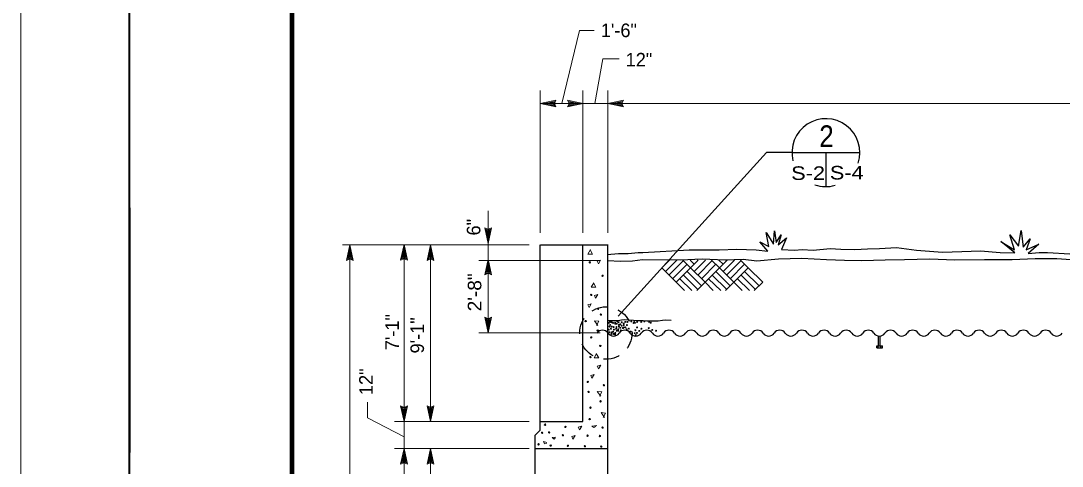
# Model space of a CAD drawing. Extents: x -22.3 to 19.7, y -11.8 to 18.2.
# Drawn here: x -22.31 to -12.72, y -5.16 to -1.06 of the extents above; entities that cross this region are included whole.
import ezdxf
from ezdxf.enums import TextEntityAlignment as Align

# ---------------------------------------------------------------- set-up
doc = ezdxf.new("R2010")
doc.units = 0
doc.header["$LTSCALE"] = 0.05
doc.linetypes.add('MEDIUM_DASHED', pattern=[4.5, 3, -1.5])
doc.layers.add('1', color=7, linetype='Continuous', lineweight=13)
doc.layers.add('2', color=7, linetype='Continuous', lineweight=13)

msp = doc.modelspace()

# ---------------------------------------------------------------- linework, layer by layer
at = {"layer": '1'}
for p, q in [((-22.30942, -11.83969), (-22.30942, 18.16031)), ((-17.32642, -1.82369), (-17.16442, -1.15069)), ((-17.16442, -1.15069), (-17.02842, -1.15069)), ((-17.02242, -1.82369), (-16.94842, -1.41369)), ((-16.94842, -1.41369), (-16.79842, -1.41369)), ((-17.52542, -3.01369), (-17.52542, -1.70369)), ((-17.13242, -3.01369), (-17.13242, -1.70369)), ((-16.90342, -3.01369), (-16.90342, -1.70369)), ((-17.52542, -1.82369), (-17.38142, -1.79269)), ((-17.48842, -1.82369), (-17.39442, -1.80369)), ((-17.45242, -1.82369), (-17.40742, -1.81369)), ((-17.40742, -1.81369), (-17.41142, -1.82369)), ((-17.39442, -1.80369), (-17.40342, -1.82369)), ((-17.13042, -1.82369), (-17.27442, -1.79269)), ((-17.16742, -1.82369), (-17.26142, -1.80369)), ((-17.25242, -1.82369), (-17.26142, -1.80369)), ((-17.20342, -1.82369), (-17.24842, -1.81469)), ((-17.24442, -1.82369), (-17.24842, -1.81469)), ((-16.90342, -1.82369), (-16.75942, -1.79269)), ((-16.86642, -1.82369), (-16.77242, -1.80369)), ((-16.83042, -1.82369), (-16.78542, -1.81369)), ((-16.78542, -1.81369), (-16.78942, -1.82369)), ((-16.77242, -1.80369), (-16.78142, -1.82369)), ((-17.52542, -1.82369), (-17.38142, -1.85469)), ((-17.48842, -1.82369), (-17.39442, -1.84369)), ((-17.45242, -1.82369), (-17.40742, -1.83269)), ((-17.41142, -1.82369), (-17.40742, -1.83269)), ((-17.40342, -1.82369), (-17.39442, -1.84369)), ((-17.13042, -1.82369), (-17.27442, -1.85469)), ((-17.16742, -1.82369), (-17.26142, -1.84369)), ((-17.26142, -1.84369), (-17.25242, -1.82369)), ((-17.20342, -1.82369), (-17.24842, -1.83369)), ((-17.24842, -1.83369), (-17.24442, -1.82369)), ((-16.90342, -1.82369), (-8.80242, -1.82369)), ((-16.90342, -1.82369), (-16.75942, -1.85469)), ((-16.86642, -1.82369), (-16.77242, -1.84369)), ((-16.83042, -1.82369), (-16.78542, -1.83269)), ((-16.78942, -1.82369), (-16.78542, -1.83269)), ((-16.78142, -1.82369), (-16.77242, -1.84369)), ((-18.00642, -3.11069), (-18.03742, -2.96669)), ((-18.00642, -3.11069), (-17.97542, -2.96669)), ((-18.00642, -3.07369), (-18.02642, -2.97969)), ((-18.02642, -2.97969), (-18.00642, -2.98869)), ((-18.00642, -3.03769), (-18.01642, -2.99269)), ((-18.01642, -2.99269), (-18.00642, -2.99669)), ((-18.00642, -3.07369), (-17.98642, -2.97969)), ((-18.00642, -2.98869), (-17.98642, -2.97969)), ((-18.00642, -3.03769), (-17.99742, -2.99269)), ((-18.00642, -2.99669), (-17.99742, -2.99269)), ((-17.62842, -3.12369), (-19.34842, -3.12369)), ((-19.27942, -3.12369), (-19.31042, -3.26769)), ((-19.27942, -3.16069), (-19.29942, -3.25469)), ((-19.27942, -3.12369), (-19.24842, -3.26769)), ((-19.27942, -3.16069), (-19.25942, -3.25469)), ((-18.78042, -3.12169), (-18.81142, -3.26569)), ((-18.78042, -3.15869), (-18.80042, -3.25269)), ((-18.78042, -3.12169), (-18.74942, -3.26569)), ((-18.78042, -3.15869), (-18.76042, -3.25269)), ((-18.53742, -3.12369), (-18.56842, -3.26769)), ((-18.53742, -3.16069), (-18.55742, -3.25469)), ((-18.53742, -4.74869), (-18.53742, -3.12369)), ((-18.53742, -3.12369), (-18.50642, -3.26769)), ((-18.53742, -3.16069), (-18.51742, -3.25469)), ((-19.27942, -3.24569), (-19.29942, -3.25469)), ((-19.27942, -3.19669), (-19.28842, -3.24169)), ((-19.27942, -3.23769), (-19.28842, -3.24169)), ((-19.27942, -3.19669), (-19.26942, -3.24169)), ((-19.26942, -3.24169), (-19.27942, -3.23769)), ((-19.25942, -3.25469), (-19.27942, -3.24569)), ((-18.78042, -3.24369), (-18.80042, -3.25269)), ((-18.78042, -3.19469), (-18.78942, -3.23969)), ((-18.78042, -3.23569), (-18.78942, -3.23969)), ((-18.78042, -3.19469), (-18.77042, -3.23969)), ((-18.77042, -3.23969), (-18.78042, -3.23569)), ((-18.76042, -3.25269), (-18.78042, -3.24369)), ((-18.53742, -3.24569), (-18.55742, -3.25469)), ((-18.53742, -3.19669), (-18.54642, -3.24169)), ((-18.53742, -3.23769), (-18.54642, -3.24169)), ((-18.53742, -3.19669), (-18.52742, -3.24169)), ((-18.52742, -3.24169), (-18.53742, -3.23769)), ((-18.51742, -3.25469), (-18.53742, -3.24569)), ((-18.00642, -3.25569), (-18.03742, -3.39969)), ((-18.00642, -3.25569), (-17.97542, -3.39969)), ((-16.97442, -3.26669), (-18.09242, -3.26669)), ((-18.00642, -3.29269), (-18.02642, -3.38669)), ((-18.00642, -3.32869), (-18.01542, -3.37369)), ((-18.00642, -3.29269), (-17.98642, -3.38669)), ((-18.00642, -3.32869), (-17.99642, -3.37369)), ((-16.40642, -3.33569), (-16.33542, -3.26469)), ((-16.37342, -3.36969), (-16.26942, -3.26469)), ((-16.34042, -3.40269), (-16.20742, -3.26869)), ((-16.30742, -3.43569), (-16.17442, -3.30269)), ((-16.27342, -3.46869), (-16.14142, -3.33569)), ((-16.14142, -3.33569), (-16.21242, -3.26469)), ((-16.10842, -3.30269), (-16.14642, -3.26469)), ((-16.14142, -3.33569), (-16.07042, -3.26469)), ((-16.14142, -3.33569), (-16.07042, -3.26469)), ((-16.00842, -3.46869), (-16.14142, -3.33569)), ((-16.10842, -3.36969), (-16.00342, -3.26469)), ((-16.07542, -3.26869), (-16.07942, -3.26469)), ((-16.07542, -3.40269), (-15.94242, -3.26869)), ((-16.04142, -3.43569), (-15.90942, -3.30269)), ((-16.00842, -3.46869), (-15.87542, -3.33569)), ((-15.87542, -3.33569), (-15.94742, -3.26469)), ((-15.84242, -3.30269), (-15.88042, -3.26469)), ((-15.87542, -3.33569), (-15.80442, -3.26469)), ((-15.84242, -3.36969), (-15.73742, -3.26469)), ((-15.80942, -3.26869), (-15.81342, -3.26469)), ((-15.80942, -3.40269), (-15.67642, -3.26869)), ((-15.77542, -3.43569), (-15.64342, -3.30269)), ((-15.74242, -3.46869), (-15.61042, -3.33569)), ((-15.61042, -3.33569), (-15.68142, -3.26469)), ((-15.47742, -3.46869), (-15.61042, -3.33569)), ((-18.00642, -3.37769), (-18.02642, -3.38669)), ((-18.00642, -3.36969), (-18.01542, -3.37369)), ((-17.99642, -3.37369), (-18.00642, -3.36969)), ((-17.98642, -3.38669), (-18.00642, -3.37769)), ((-16.13142, -3.54569), (-16.24042, -3.43569)), ((-16.07542, -3.53469), (-16.20742, -3.40269)), ((-16.04142, -3.50169), (-16.17442, -3.36969)), ((-15.86442, -3.54569), (-15.97542, -3.43569)), ((-15.80842, -3.53469), (-15.94242, -3.40269)), ((-15.77542, -3.50169), (-15.90942, -3.36969)), ((-15.59942, -3.54569), (-15.70942, -3.43569)), ((-15.54342, -3.53469), (-15.67642, -3.40269)), ((-15.51042, -3.50169), (-15.64342, -3.36969)), ((-16.08542, -3.54569), (-16.00842, -3.46869)), ((-15.93242, -3.54569), (-16.00842, -3.46869)), ((-15.81942, -3.54569), (-15.74242, -3.46869)), ((-15.55442, -3.54569), (-15.47742, -3.46869)), ((-18.00642, -3.93369), (-18.03742, -3.78969)), ((-18.00642, -3.89669), (-18.02642, -3.80269)), ((-18.02642, -3.80269), (-18.00642, -3.81169)), ((-18.00642, -3.86069), (-18.01642, -3.81569)), ((-18.01642, -3.81569), (-18.00642, -3.81969)), ((-18.00642, -3.93369), (-17.97542, -3.78969)), ((-18.00642, -3.89669), (-17.98642, -3.80269)), ((-18.00642, -3.81169), (-17.98642, -3.80269)), ((-18.00642, -3.86069), (-17.99742, -3.81569)), ((-18.00642, -3.81969), (-17.99742, -3.81569)), ((-16.97442, -3.93369), (-18.09242, -3.93369)), ((-18.78042, -4.74969), (-18.81142, -4.60569)), ((-18.78042, -4.71269), (-18.80042, -4.61869)), ((-18.80042, -4.61869), (-18.78042, -4.62769)), ((-18.78042, -4.67669), (-18.79042, -4.63169)), ((-18.79042, -4.63169), (-18.78042, -4.63569)), ((-18.78042, -4.74969), (-18.74942, -4.60569)), ((-18.78042, -4.71269), (-18.76042, -4.61869)), ((-18.78042, -4.62769), (-18.76042, -4.61869)), ((-18.78042, -4.67669), (-18.77142, -4.63169)), ((-18.78042, -4.63569), (-18.77142, -4.63169)), ((-18.53742, -4.74869), (-18.56842, -4.60469)), ((-18.53742, -4.71169), (-18.55742, -4.61769)), ((-18.55742, -4.61769), (-18.53742, -4.62669)), ((-18.53742, -4.67569), (-18.54742, -4.63069)), ((-18.54742, -4.63069), (-18.53742, -4.63469)), ((-18.53742, -4.74869), (-18.50642, -4.60469)), ((-18.53742, -4.71169), (-18.51742, -4.61769)), ((-18.53742, -4.62669), (-18.51742, -4.61769)), ((-18.53742, -4.67569), (-18.52842, -4.63069)), ((-18.53742, -4.63469), (-18.52842, -4.63069)), ((-17.62842, -4.74969), (-18.86842, -4.74969)), ((-17.62842, -4.99969), (-18.86842, -4.99969)), ((-18.78042, -4.99969), (-18.81142, -5.14369)), ((-18.78042, -5.03669), (-18.80042, -5.13069)), ((-18.78042, -5.07269), (-18.78942, -5.11769)), ((-18.78042, -4.99969), (-18.74942, -5.14369)), ((-18.78042, -5.03669), (-18.76042, -5.13069)), ((-18.78042, -5.07269), (-18.77042, -5.11769)), ((-18.53742, -4.99969), (-18.56842, -5.14369)), ((-18.53742, -5.03669), (-18.55742, -5.13069)), ((-18.53742, -5.07269), (-18.54642, -5.11769)), ((-18.53742, -7.65769), (-18.53742, -4.99969)), ((-18.53742, -4.99969), (-18.50642, -5.14369)), ((-18.53742, -5.03669), (-18.51742, -5.13069)), ((-18.53742, -5.07269), (-18.52742, -5.11769)), ((-18.78042, -5.12169), (-18.80042, -5.13069)), ((-18.78042, -5.11369), (-18.78942, -5.11769)), ((-18.77042, -5.11769), (-18.78042, -5.11369)), ((-18.76042, -5.13069), (-18.78042, -5.12169)), ((-18.53742, -5.12169), (-18.55742, -5.13069)), ((-18.53742, -5.11369), (-18.54642, -5.11769)), ((-18.52742, -5.11769), (-18.53742, -5.11369)), ((-18.51742, -5.13069), (-18.53742, -5.12169))]:
    msp.add_line(p, q, dxfattribs=at)
at = {"layer": '1', "lineweight": 25}
for p, q in [((-15.44342, -2.27569), (-16.80842, -3.77969)), ((-15.20742, -2.27569), (-15.44342, -2.27569)), ((-17.52542, -4.82969), (-17.52542, -3.12369)), ((-17.52242, -3.12369), (-16.90142, -3.12369)), ((-17.13242, -4.75069), (-17.13242, -3.12369)), ((-16.90342, -7.91969), (-16.90342, -3.12569)), ((-14.41042, -4.05469), (-14.41042, -3.96369)), ((-14.39442, -4.05469), (-14.39442, -3.96369)), ((-14.42642, -4.05469), (-14.37542, -4.05469)), ((-14.42642, -4.07169), (-14.42642, -4.05469)), ((-14.42642, -4.07169), (-14.37542, -4.07169)), ((-14.41342, -4.07169), (-14.41342, -4.05469)), ((-14.39042, -4.07169), (-14.39042, -4.05469)), ((-14.37542, -4.07169), (-14.37542, -4.05469)), ((-17.52742, -4.74969), (-17.13342, -4.74969)), ((-17.57242, -4.87469), (-17.52542, -4.82969)), ((-17.57242, -7.65769), (-17.57242, -4.87469)), ((-17.57242, -4.99969), (-16.90342, -4.99969))]:
    msp.add_line(p, q, dxfattribs=at)
at = {"layer": '1', "lineweight": 40}
msp.add_line((-21.30842, -2.78469), (-21.30842, -5.03469), dxfattribs=at)
msp.add_lwpolyline([(-21.30942, -10.83969), (-21.30942, 17.16031), (18.69058, 17.16031), (18.69058, -10.83969)], close=True, dxfattribs=at)
at = {"layer": '1', "lineweight": 90}
msp.add_lwpolyline([(-19.80942, 16.66031), (18.19058, 16.66031), (18.19058, -10.33969), (-19.80942, -10.33969)], close=True, dxfattribs=at)
at = {"layer": '1'}
for points in [[(-17.38142, -1.79269), (-17.39542, -1.82369), (-17.38142, -1.85469)], [(-17.27442, -1.85469), (-17.26042, -1.82369), (-17.27442, -1.79269)], [(-16.75942, -1.79269), (-16.77342, -1.82369), (-16.75942, -1.85469)], [(-17.52542, -1.82369), (-17.13042, -1.82369), (-16.90342, -1.82369)], [(-18.00642, -3.93369), (-18.00642, -3.25569), (-18.00642, -3.11069), (-18.00642, -2.81069)], [(-18.03742, -2.96669), (-18.00642, -2.98069), (-17.97542, -2.96669)], [(-19.27942, -8.39369), (-19.27942, -7.65769), (-19.27942, -3.12369)], [(-18.78042, -7.65769), (-18.78042, -4.99969), (-18.78042, -4.74969), (-18.78042, -3.12169)], [(-19.24842, -3.26769), (-19.27942, -3.25369), (-19.31042, -3.26769)], [(-18.74942, -3.26569), (-18.78042, -3.25169), (-18.81142, -3.26569)], [(-18.50642, -3.26769), (-18.53742, -3.25369), (-18.56842, -3.26769)], [(-16.19742, -3.54569), (-16.27342, -3.46869), (-16.40642, -3.33569)], [(-15.66642, -3.54569), (-15.87542, -3.33569), (-15.80442, -3.26469)], [(-17.97542, -3.39969), (-18.00642, -3.38569), (-18.03742, -3.39969)], [(-18.03742, -3.78969), (-18.00642, -3.80369), (-17.97542, -3.78969)], [(-18.78042, -4.89169), (-19.11642, -4.71569), (-19.11642, -4.57269)], [(-18.81142, -4.60569), (-18.78042, -4.61969), (-18.74942, -4.60569)], [(-18.56842, -4.60469), (-18.53742, -4.61869), (-18.50642, -4.60469)], [(-18.74942, -5.14369), (-18.78042, -5.12969), (-18.81142, -5.14369)], [(-18.50642, -5.14369), (-18.53742, -5.12969), (-18.56842, -5.14369)]]:
    msp.add_lwpolyline(points, dxfattribs=at)
at = {"layer": '1', "lineweight": 25}
for points in [[(-16.90942, -3.21369), (-16.80642, -3.20469), (-16.71742, -3.20369), (-16.62342, -3.19469), (-16.58242, -3.19569), (-16.15342, -3.16969), (-15.87842, -3.17069), (-15.71642, -3.16269), (-15.53742, -3.16869), (-15.43042, -3.18169), (-15.50342, -3.09569), (-15.42142, -3.14069), (-15.44542, -3.01169), (-15.37842, -3.11669), (-15.36942, -2.99369), (-15.35242, -3.10369), (-15.30842, -3.03069), (-15.33642, -3.12369), (-15.25742, -3.05869), (-15.30542, -3.16569), (-15.18442, -3.17169), (-15.11342, -3.16569), (-15.01342, -3.17169), (-14.85742, -3.15769), (-14.75642, -3.16369), (-14.62942, -3.16769), (-14.51142, -3.16169), (-14.40242, -3.15769), (-14.24642, -3.14869), (-14.06042, -3.17269), (-13.82042, -3.19169), (-13.64242, -3.18669), (-13.47042, -3.17969), (-13.29042, -3.19469), (-13.15642, -3.19869), (-13.28442, -3.09269), (-13.15742, -3.16969), (-13.20242, -3.03069), (-13.12242, -3.13769), (-13.09742, -2.99269), (-13.07742, -3.14469), (-13.01442, -3.06769), (-13.05242, -3.16969), (-12.93542, -3.11769), (-13.03342, -3.20269), (-12.93142, -3.19469), (-12.85542, -3.19469), (-12.64942, -3.20769)], [(-16.90242, -3.26669), (-16.79142, -3.27369), (-16.67542, -3.27069), (-16.58342, -3.25769), (-16.23342, -3.26169), (-16.03442, -3.25369), (-15.82242, -3.26169), (-15.65842, -3.25569), (-15.53142, -3.27169), (-15.33142, -3.25369), (-15.11542, -3.24569), (-14.88942, -3.25769), (-14.72342, -3.26569), (-14.56542, -3.26969), (-14.34842, -3.26069), (-14.17242, -3.25969), (-13.93842, -3.25369), (-13.70942, -3.26269), (-13.43442, -3.25769), (-13.18042, -3.25869), (-12.96742, -3.24869), (-12.76842, -3.25069), (-12.50742, -3.26669)], [(-16.90442, -3.82069), (-16.87342, -3.82069), (-16.84042, -3.82069), (-16.80842, -3.81969), (-16.77742, -3.81569), (-16.74742, -3.81169), (-16.70842, -3.81569), (-16.66742, -3.81769), (-16.63142, -3.82069), (-16.57942, -3.82069), (-16.54542, -3.82269), (-16.48442, -3.82269), (-16.44042, -3.82469), (-16.39942, -3.81869), (-16.37142, -3.81269), (-16.32042, -3.81769)]]:
    msp.add_lwpolyline(points, dxfattribs=at)
at = {"layer": '1', "linetype": 'MEDIUM_DASHED', "lineweight": 25}
msp.add_circle((-16.92142, -3.93569), 0.24086, dxfattribs=at)
at = {"layer": '1'}
for centre in [(-16.88392, -3.83369), (-16.86892, -3.83669), (-16.81692, -3.82969), (-16.80392, -3.83669), (-16.77492, -3.83669), (-16.74292, -3.83369), (-16.72292, -3.83369), (-16.68792, -3.82969), (-16.66092, -3.83369), (-16.63392, -3.83369), (-16.59592, -3.83369), (-16.56692, -3.82969), (-16.52192, -3.83369), (-16.89492, -3.84269), (-16.89492, -3.90369), (-16.88892, -3.87669), (-16.88892, -3.92769), (-16.88192, -3.86069), (-16.87492, -3.89669), (-16.86892, -3.87669), (-16.86892, -3.92969), (-16.85492, -3.84269), (-16.85492, -3.92369), (-16.85092, -3.88069), (-16.84792, -3.90369), (-16.83692, -3.84069), (-16.83492, -3.84969), (-16.83492, -3.93469), (-16.82792, -3.89669), (-16.82392, -3.88069), (-16.82192, -3.84969), (-16.82192, -3.91469), (-16.80792, -3.90069), (-16.80792, -3.91469), (-16.80092, -3.86069), (-16.80092, -3.87669), (-16.78792, -3.85469), (-16.78792, -3.88769), (-16.78392, -3.90969), (-16.77692, -3.86969), (-16.76392, -3.88969), (-16.75692, -3.84769), (-16.75692, -3.86269), (-16.75692, -3.88369), (-16.74092, -3.88369), (-16.72992, -3.90069), (-16.72792, -3.86269), (-16.70992, -3.89469), (-16.69392, -3.92169), (-16.66692, -3.84269), (-16.65392, -3.84069), (-16.64992, -3.90969), (-16.63592, -3.93469), (-16.63392, -3.88369), (-16.61392, -3.91669), (-16.59392, -3.89669), (-16.52692, -3.88969), (-16.50892, -3.84069), (-16.49492, -3.90769), (-16.45992, -3.91469), (-16.87092, -3.94369), (-16.85092, -3.94369), (-16.83692, -3.94769), (-16.65592, -3.93669), (-16.64692, -3.95469)]:
    msp.add_circle(centre, 0.0043, dxfattribs=at)
at = {"layer": '1', "lineweight": 25}
for centre, start, end in [((-16.95242, -3.97119), 34.0772, 145.92281), ((-16.74842, -3.97119), 34.0772, 145.92281), ((-16.54442, -3.97119), 34.0772, 145.92281), ((-16.34042, -3.97119), 34.0772, 145.92281), ((-16.13642, -3.97119), 34.0772, 145.92281), ((-15.93242, -3.97119), 34.0772, 145.92281), ((-15.72842, -3.97119), 34.0772, 145.92281), ((-15.52442, -3.97119), 34.0772, 145.92281), ((-15.32042, -3.97119), 34.0772, 145.92281), ((-15.11642, -3.97119), 34.0772, 145.92281), ((-14.91242, -3.97119), 34.0772, 145.92281), ((-14.70842, -3.97119), 34.0772, 145.92281), ((-14.50442, -3.97119), 34.0772, 145.92281), ((-14.30042, -3.97119), 34.0772, 145.92281), ((-14.09642, -3.97119), 34.0772, 145.92281), ((-13.89242, -3.97119), 34.0772, 145.92281), ((-13.68842, -3.97119), 34.0772, 145.92281), ((-13.48442, -3.97119), 34.0772, 145.92281), ((-13.28042, -3.97119), 34.0772, 145.92281), ((-13.07642, -3.97119), 34.0772, 145.92281), ((-12.87242, -3.97119), 34.0772, 145.92281), ((-16.85042, -3.90219), 214.0772, 325.92281), ((-16.64642, -3.90219), 214.0772, 325.92281), ((-16.44242, -3.90219), 214.0772, 325.92281), ((-16.23842, -3.90219), 214.0772, 325.92281), ((-16.03442, -3.90219), 214.0772, 325.92281), ((-15.83042, -3.90219), 214.0772, 325.92281), ((-15.62642, -3.90219), 214.0772, 325.92281), ((-15.42242, -3.90219), 214.0772, 325.92281), ((-15.21842, -3.90219), 214.0772, 325.92281), ((-15.01442, -3.90219), 214.0772, 325.92281), ((-14.81042, -3.90219), 214.0772, 325.92281), ((-14.60642, -3.90219), 214.0772, 325.92281), ((-14.40242, -3.90219), 214.0772, 325.92281), ((-14.19842, -3.90219), 214.0772, 325.92281), ((-13.99442, -3.90219), 214.0772, 325.92281), ((-13.79042, -3.90219), 214.0772, 325.92281), ((-13.58642, -3.90219), 214.0772, 325.92281), ((-13.38242, -3.90219), 214.0772, 325.92281), ((-13.17842, -3.90219), 214.0772, 325.92281), ((-12.97442, -3.90219), 214.0772, 325.92281), ((-12.77042, -3.90219), 214.0772, 325.92281)]:
    msp.add_arc(centre, 0.06157, start, end, dxfattribs=at)
at = {"layer": '2', "lineweight": 25}
for p, q in [((-15.20742, -2.27569), (-14.58342, -2.27569)), ((-14.89542, -2.27569), (-14.89542, -2.58769))]:
    msp.add_line(p, q, dxfattribs=at)
at = {"layer": '2'}
for points in [[(-17.06442, -3.17469), (-17.04442, -3.20869), (-17.08842, -3.20869), (-17.06442, -3.16769)], [(-17.03342, -3.47969), (-17.01342, -3.51369), (-17.05742, -3.51369), (-17.03342, -3.47269)], [(-17.00642, -3.86669), (-16.98642, -3.82669), (-17.02742, -3.82269), (-16.99642, -3.86669)], [(-17.00642, -4.13069), (-16.98642, -4.16469), (-17.03042, -4.16469), (-17.00642, -4.12369)], [(-16.97942, -4.51769), (-16.95942, -4.47769), (-17.00042, -4.47369), (-16.96942, -4.51769)], [(-16.94542, -4.71169), (-16.92542, -4.67169), (-16.96642, -4.66769), (-16.93542, -4.71169)], [(-17.01342, -4.79269), (-17.03342, -4.80569), (-17.05042, -4.79269), (-17.00342, -4.78569)], [(-17.46542, -4.94769), (-17.48542, -4.95469), (-17.49542, -4.93369), (-17.46542, -4.94369)], [(-17.38442, -4.89669), (-17.39842, -4.91369), (-17.41542, -4.89669), (-17.38842, -4.89369)]]:
    msp.add_lwpolyline(points, dxfattribs=at)
for points in [[(-16.97042, -3.26369), (-16.99042, -3.29769), (-17.00142, -3.27369)], [(-16.99642, -3.58069), (-17.01642, -3.61469), (-17.02742, -3.59069)], [(-17.05642, -3.66669), (-17.07642, -3.70069), (-17.08842, -3.67669)], [(-16.96942, -4.23169), (-16.98942, -4.26569), (-17.00042, -4.24169)], [(-17.02942, -4.31769), (-17.04942, -4.35169), (-17.06142, -4.32769)], [(-17.14442, -4.79269), (-17.16442, -4.82669), (-17.17542, -4.80269)], [(-17.20442, -4.87869), (-17.22442, -4.91269), (-17.23642, -4.88869)]]:
    msp.add_lwpolyline(points, close=True, dxfattribs=at)
for centre in [(-17.06992, -3.28519), (-16.95192, -3.40819), (-17.05692, -3.58419), (-16.99292, -3.71119), (-17.10792, -3.82619), (-16.96692, -3.76519), (-16.99692, -3.91319), (-17.05692, -3.97619), (-16.97292, -4.05419), (-17.06392, -4.15719), (-17.08792, -4.38519), (-16.93992, -4.41619), (-17.08092, -4.47719), (-16.96992, -4.56419), (-17.06392, -4.62219), (-17.48192, -4.77919), (-17.29392, -4.79919), (-17.07092, -4.72819), (-17.50892, -4.85319), (-17.44492, -4.85019), (-17.31692, -4.87619), (-17.08992, -4.88019), (-16.97692, -4.88319), (-16.95192, -4.80519), (-17.54192, -4.96019), (-17.42992, -4.97119), (-17.27092, -4.97319), (-17.11492, -4.97719), (-16.96492, -4.98019)]:
    msp.add_circle(centre, 0.0065, dxfattribs=at)
at = {"layer": '2', "lineweight": 25}
for start, end in [(341.96976, 193.81208), (251.04049, 285.74671)]:
    msp.add_arc((-14.89542, -2.27569), 0.3125, start, end, dxfattribs=at)

# ---------------------------------------------------------------- texts
at = {"layer": '1'}
for s, p in [('1\'-6"', (-16.96842, -1.21269)), ('12"', (-16.73942, -1.48269))]:
    msp.add_text(s, height=0.125, dxfattribs=at).set_placement(p)
for s, p in [('6"', (-18.07742, -2.96169)), ('7\'-1"', (-18.82742, -3.92769)), ('9\'-1"', (-18.59642, -3.95719))]:
    msp.add_text(s, height=0.125, rotation=90, dxfattribs=at).set_placement(p, align=Align.CENTER)
at = {"layer": '1', "width": 1.05}
msp.add_text('2\'-8"', height=0.125, rotation=90, dxfattribs=at).set_placement((-18.06842, -3.56119), align=Align.CENTER)
at = {"layer": '1'}
msp.add_text('12"', height=0.125, rotation=90, dxfattribs=at).set_placement((-19.06842, -4.50669))
at = {"layer": '2'}
for s, height, width, p in [('2', 0.2, 0.9, (-14.88992, -2.22469)), ('S-4', 0.125, 1.2, (-14.70342, -2.52269)), ('S-2', 0.125, 1.2, (-15.05942, -2.52669))]:
    msp.add_text(s, height=height, dxfattribs=dict(at, width=width)).set_placement(p, align=Align.CENTER)

doc.saveas('drawing.dxf')
